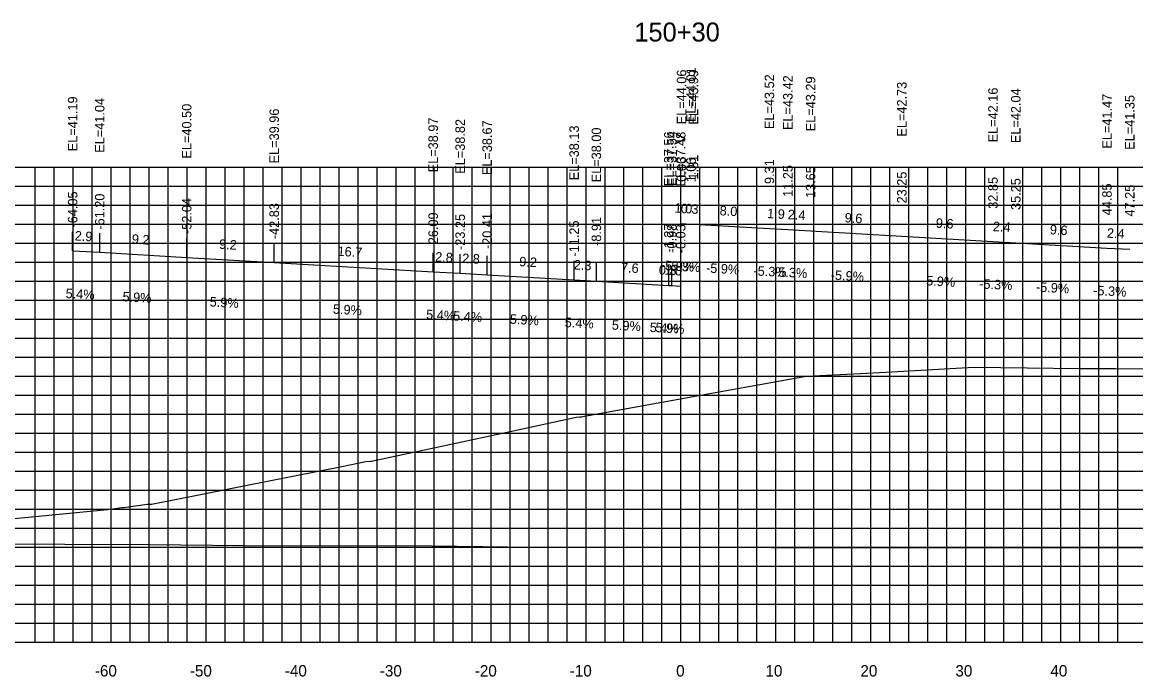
# Model space of a CAD drawing. Extents: x 1800880 to 1818864, y 245271 to 250560.
# Drawn here: x 1808999.1 to 1809116.3, y 249645.6 to 249714.4 of the extents above; entities that cross this region are included whole.
import ezdxf

# ---------------------------------------------------------------- set-up
doc = ezdxf.new("R2010")
doc.units = 0
for name, color, linetype in [('ANNO-TXT', 7, 'Continuous'), ('AXIS', 7, 'Continuous'), ('CL-CNST', 7, 'Continuous'), ('DESIGN - DRAINAGE - Bridges', 7, 'Continuous'), ('Level 32', 7, 'Continuous'), ('Level 37', 7, 'Continuous'), ('Level 46', 7, 'Continuous'), ('Level 62', 7, 'Continuous'), ('SHT-BDR', 7, 'Continuous')]:
    doc.layers.add(name, color=color, linetype=linetype)

msp = doc.modelspace()

# ---------------------------------------------------------------- linework, layer by layer
at = {"layer": 'AXIS'}
msp.add_lwpolyline([(1809068.52, 249693.28), (1809069.52, 249693.22), (1809069.77, 249693.21), (1809077.77, 249692.74), (1809079.71, 249692.64), (1809082.11, 249692.51), (1809091.71, 249691.94), (1809101.31, 249691.38), (1809103.71, 249691.25), (1809113.31, 249690.69), (1809115.71, 249690.56)], dxfattribs=at)
at = {"layer": 'CL-CNST'}
msp.add_lwpolyline([(1808995.35, 249661.96), (1809008.42, 249663.24), (1809009.59, 249663.39), (1809009.81, 249663.41), (1809010.79, 249663.54), (1809012.26, 249663.74), (1809012.28, 249663.75), (1809012.71, 249663.74), (1809012.73, 249663.74), (1809017.88, 249664.77), (1809020.67, 249665.32), (1809022.44, 249665.67), (1809032.75, 249667.7), (1809035.28, 249668.24), (1809035.78, 249668.26), (1809035.86, 249668.26), (1809050.96, 249671.5), (1809051.27, 249671.56), (1809057.44, 249672.92), (1809057.81, 249672.93), (1809058.01, 249672.94), (1809058.3, 249673.01), (1809070.52, 249675.23), (1809081.63, 249677.21), (1809087.35, 249677.5), (1809090.01, 249677.64), (1809096.79, 249678.01), (1809099.34, 249678.15), (1809104.9, 249678.09), (1809110.43, 249678.04), (1809114.2, 249678.01), (1809121.86, 249677.94)], dxfattribs=at)
at = {"layer": 'DESIGN - DRAINAGE - Bridges'}
for p, q in [((1808918.46, 249649.22), (1809218.46, 249649.22)), ((1809008.46, 249649.16), (1809008.46, 249649.22)), ((1809018.46, 249649.16), (1809018.46, 249649.22)), ((1809028.46, 249649.16), (1809028.46, 249649.22)), ((1809038.46, 249649.16), (1809038.46, 249649.22)), ((1809048.46, 249649.16), (1809048.46, 249649.22)), ((1809058.46, 249649.16), (1809058.46, 249649.22)), ((1809068.46, 249649.16), (1809068.46, 249649.22)), ((1809078.46, 249649.16), (1809078.46, 249649.22)), ((1809088.46, 249649.16), (1809088.46, 249649.22)), ((1809098.46, 249649.16), (1809098.46, 249649.22)), ((1809108.46, 249649.16), (1809108.46, 249649.22))]:
    msp.add_line(p, q, dxfattribs=at)
at = {"layer": 'Level 37'}
for p, q in [((1809004.41, 249690.4), (1809004.41, 249692.4)), ((1809007.26, 249690.25), (1809007.26, 249692.25)), ((1809016.42, 249689.71), (1809016.42, 249691.71)), ((1809025.63, 249689.17), (1809025.63, 249691.17)), ((1809042.37, 249688.19), (1809042.37, 249690.19)), ((1809045.21, 249688.04), (1809045.21, 249690.04)), ((1809048.05, 249687.88), (1809048.05, 249689.88)), ((1809057.21, 249687.35), (1809057.21, 249689.35)), ((1809059.55, 249687.22), (1809059.55, 249689.22)), ((1809067.18, 249686.77), (1809067.18, 249688.77)), ((1809067.48, 249686.75), (1809067.48, 249688.75)), ((1809068.43, 249686.7), (1809068.43, 249688.7))]:
    msp.add_line(p, q, dxfattribs=at)
at = {"layer": 'Level 46'}
for p, q in [((1808918.46, 249699.22), (1809218.46, 249699.22)), ((1809000.46, 249649.22), (1809000.46, 249699.22)), ((1809002.46, 249649.22), (1809002.46, 249699.22)), ((1809004.46, 249649.22), (1809004.46, 249699.22)), ((1809006.46, 249649.22), (1809006.46, 249699.22)), ((1809008.46, 249649.22), (1809008.46, 249699.22)), ((1809010.46, 249649.22), (1809010.46, 249699.22)), ((1809012.46, 249649.22), (1809012.46, 249699.22)), ((1809014.46, 249649.22), (1809014.46, 249699.22)), ((1809016.46, 249649.22), (1809016.46, 249699.22)), ((1809018.46, 249649.22), (1809018.46, 249699.22)), ((1809020.46, 249649.22), (1809020.46, 249699.22)), ((1809022.46, 249649.22), (1809022.46, 249699.22)), ((1809024.46, 249649.22), (1809024.46, 249699.22)), ((1809026.46, 249649.22), (1809026.46, 249699.22)), ((1809028.46, 249649.22), (1809028.46, 249699.22)), ((1809030.46, 249649.22), (1809030.46, 249699.22)), ((1809032.46, 249649.22), (1809032.46, 249699.22)), ((1809034.46, 249649.22), (1809034.46, 249699.22)), ((1809036.46, 249649.22), (1809036.46, 249699.22)), ((1809038.46, 249649.22), (1809038.46, 249699.22)), ((1809040.46, 249649.22), (1809040.46, 249699.22)), ((1809042.46, 249649.22), (1809042.46, 249699.22)), ((1809044.46, 249649.22), (1809044.46, 249699.22)), ((1809046.46, 249649.22), (1809046.46, 249699.22)), ((1809048.46, 249649.22), (1809048.46, 249699.22)), ((1809050.46, 249649.22), (1809050.46, 249699.22)), ((1809052.46, 249649.22), (1809052.46, 249699.22)), ((1809054.46, 249649.22), (1809054.46, 249699.22)), ((1809056.46, 249649.22), (1809056.46, 249699.22)), ((1809058.46, 249649.22), (1809058.46, 249699.22)), ((1809060.46, 249649.22), (1809060.46, 249699.22)), ((1809062.46, 249649.22), (1809062.46, 249699.22)), ((1809064.46, 249649.22), (1809064.46, 249699.22)), ((1809066.46, 249649.22), (1809066.46, 249699.22)), ((1809068.46, 249649.22), (1809068.46, 249699.22)), ((1809070.46, 249649.22), (1809070.46, 249699.22)), ((1809072.46, 249649.22), (1809072.46, 249699.22)), ((1809074.46, 249649.22), (1809074.46, 249699.22)), ((1809076.46, 249649.22), (1809076.46, 249699.22)), ((1809078.46, 249649.22), (1809078.46, 249699.22)), ((1809080.46, 249649.22), (1809080.46, 249699.22)), ((1809082.46, 249649.22), (1809082.46, 249699.22)), ((1809084.46, 249649.22), (1809084.46, 249699.22)), ((1809086.46, 249649.22), (1809086.46, 249699.22)), ((1809088.46, 249649.22), (1809088.46, 249699.22)), ((1809090.46, 249649.22), (1809090.46, 249699.22)), ((1809092.46, 249649.22), (1809092.46, 249699.22)), ((1809094.46, 249649.22), (1809094.46, 249699.22)), ((1809096.46, 249649.22), (1809096.46, 249699.22)), ((1809098.46, 249649.22), (1809098.46, 249699.22)), ((1809100.46, 249649.22), (1809100.46, 249699.22)), ((1809102.46, 249649.22), (1809102.46, 249699.22)), ((1809104.46, 249649.22), (1809104.46, 249699.22)), ((1809106.46, 249649.22), (1809106.46, 249699.22)), ((1809108.46, 249649.22), (1809108.46, 249699.22)), ((1809110.46, 249649.22), (1809110.46, 249699.22)), ((1809112.46, 249649.22), (1809112.46, 249699.22)), ((1809114.46, 249649.22), (1809114.46, 249699.22)), ((1808918.46, 249697.22), (1809218.46, 249697.22)), ((1808918.46, 249695.22), (1809218.46, 249695.22)), ((1808918.46, 249693.22), (1809218.46, 249693.22)), ((1808918.46, 249691.22), (1809218.46, 249691.22)), ((1808918.46, 249689.22), (1809218.46, 249689.22)), ((1808918.46, 249687.22), (1809218.46, 249687.22)), ((1808918.46, 249685.22), (1809218.46, 249685.22)), ((1808918.46, 249683.22), (1809218.46, 249683.22)), ((1808918.46, 249681.22), (1809218.46, 249681.22)), ((1808918.46, 249679.22), (1809218.46, 249679.22)), ((1808918.46, 249677.22), (1809218.46, 249677.22)), ((1808918.46, 249675.22), (1809218.46, 249675.22)), ((1808918.46, 249673.22), (1809218.46, 249673.22)), ((1808918.46, 249671.22), (1809218.46, 249671.22)), ((1808918.46, 249669.22), (1809218.46, 249669.22)), ((1808918.46, 249667.22), (1809218.46, 249667.22)), ((1808918.46, 249665.22), (1809218.46, 249665.22)), ((1808918.46, 249663.22), (1809218.46, 249663.22)), ((1808918.46, 249661.22), (1809218.46, 249661.22)), ((1808918.46, 249659.22), (1809218.46, 249659.22)), ((1808918.46, 249657.22), (1809218.46, 249657.22)), ((1808918.46, 249655.22), (1809218.46, 249655.22)), ((1808918.46, 249653.22), (1809218.46, 249653.22)), ((1808918.46, 249651.22), (1809218.46, 249651.22)), ((1808918.46, 249649.22), (1809218.46, 249649.22))]:
    msp.add_line(p, q, dxfattribs=at)
at = {"layer": 'Level 62'}
for points in [[(1809004.41, 249690.4), (1809007.26, 249690.25), (1809016.42, 249689.71), (1809025.63, 249689.17), (1809042.37, 249688.19), (1809045.21, 249688.04), (1809048.05, 249687.88), (1809057.21, 249687.35), (1809059.55, 249687.22), (1809067.18, 249686.77), (1809067.48, 249686.75), (1809068.43, 249686.7)], [(1808918.46, 249660.55), (1808939.2, 249660.09), (1808950.74, 249659.99), (1808966.95, 249659.79), (1808982.05, 249659.69), (1808994.71, 249659.57), (1809012.42, 249659.49), (1809022.47, 249659.41), (1809042.19, 249659.35), (1809050.22, 249659.27), (1809071.53, 249659.24), (1809077.98, 249659.19), (1809100.58, 249659.19), (1809105.73, 249659.16), (1809129.4, 249659.19), (1809133.49, 249659.16), (1809158.05, 249659.24), (1809161.24, 249659.23), (1809186.58, 249659.35), (1809189, 249659.35), (1809214.99, 249659.5), (1809216.75, 249659.47), (1809218.46, 249659.48)]]:
    msp.add_lwpolyline(points, dxfattribs=at)

# ---------------------------------------------------------------- texts
for s, p in [('-60', (1809006.75, 249645.62)), ('-50', (1809016.75, 249645.62)), ('-40', (1809026.75, 249645.62)), ('-30', (1809036.75, 249645.62)), ('-20', (1809046.75, 249645.62)), ('-10', (1809056.75, 249645.62)), ('0', (1809067.95, 249645.62)), ('10', (1809077.35, 249645.62)), ('20', (1809087.35, 249645.62)), ('30', (1809097.35, 249645.62)), ('40', (1809107.35, 249645.62))]:
    msp.add_text(s, height=1.2).set_placement(p)
at = {"layer": 'ANNO-TXT'}
for s, rotation, p in [('1.0', 356.6368, (1809067.76, 249694.43)), ('0.3', 356.9763, (1809068.42, 249694.38)), ('8.0', 356.6368, (1809072.51, 249694.15)), ('1.9', 356.9763, (1809077.51, 249693.85)), ('2.4', 356.9763, (1809079.68, 249693.74)), ('9.6', 356.6368, (1809085.67, 249693.4)), ('9.6', 356.6368, (1809095.27, 249692.84)), ('2.9', 356.9237, (1809004.61, 249691.5)), ('2.4', 356.9763, (1809101.28, 249692.48)), ('9.6', 356.6368, (1809107.27, 249692.15)), ('2.4', 356.9763, (1809113.28, 249691.79)), ('9.2', 356.6368, (1809010.62, 249691.16)), ('9.2', 356.6368, (1809019.81, 249690.62)), ('16.7', 356.6368, (1809032.28, 249689.88)), ('2.8', 356.9237, (1809042.56, 249689.28)), ('2.8', 356.9237, (1809045.4, 249689.13)), ('9.2', 356.6368, (1809051.41, 249688.79)), ('2.3', 356.9237, (1809057.15, 249688.45)), ('7.6', 356.6368, (1809062.12, 249688.17)), ('0.3', 356.9237, (1809066.11, 249687.93)), ('-5.9%', 356.6368, (1809066.32, 249688.4)), ('-5.3%', 356.9763, (1809066.97, 249688.35)), ('-5.9%', 356.6368, (1809071.07, 249688.12)), ('1.0', 356.6368, (1809066.7, 249687.9)), ('-5.3%', 356.9763, (1809076.07, 249687.82)), ('-5.3%', 356.9763, (1809078.24, 249687.71)), ('-5.9%', 356.6368, (1809084.21, 249687.38)), ('-5.9%', 356.6368, (1809093.81, 249686.81)), ('-5.3%', 356.9763, (1809099.84, 249686.45)), ('-5.9%', 356.6368, (1809105.81, 249686.12)), ('-5.3%', 356.9763, (1809111.84, 249685.76)), ('5.4%', 356.9237, (1809003.65, 249685.44)), ('5.9%', 356.6368, (1809009.64, 249685.1)), ('5.9%', 356.6368, (1809018.82, 249684.56)), ('5.9%', 356.6368, (1809031.79, 249683.8)), ('5.4%', 356.9237, (1809041.61, 249683.22)), ('5.4%', 356.9237, (1809044.45, 249683.07)), ('5.9%', 356.6368, (1809050.42, 249682.74)), ('5.4%', 356.9237, (1809056.2, 249682.39)), ('5.9%', 356.6368, (1809061.16, 249682.12)), ('5.4%', 356.9237, (1809065.15, 249681.87)), ('5.9%', 356.6368, (1809065.75, 249681.85))]:
    msp.add_text(s, height=1, rotation=rotation, dxfattribs=at).set_placement(p)
at = {"layer": 'DESIGN - DRAINAGE - Bridges'}
msp.add_text('>', height=1.5, dxfattribs=at).set_placement((1809067.85, 249701.47))
at = {"layer": 'Level 32'}
msp.add_text('150+30', height=2, dxfattribs=at).set_placement((1809063.55, 249712.42))
at = {"layer": 'SHT-BDR'}
for s, p in [('EL=44.06', (1809069.02, 249703.71)), ('EL=44.01', (1809070.02, 249703.95)), ('EL=43.99', (1809070.27, 249703.68)), ('EL=43.52', (1809078.27, 249703.21)), ('EL=43.42', (1809080.21, 249703.11)), ('EL=43.29', (1809082.61, 249702.98)), ('EL=42.73', (1809092.21, 249702.42)), ('EL=41.19', (1809004.91, 249700.88)), ('EL=42.16', (1809101.81, 249701.81)), ('EL=42.04', (1809104.21, 249701.73)), ('EL=41.47', (1809113.81, 249701.16)), ('EL=41.35', (1809116.21, 249701.03)), ('EL=41.04', (1809007.76, 249700.72)), ('EL=40.50', (1809016.92, 249700.11)), ('EL=39.96', (1809026.13, 249699.6)), ('EL=38.97', (1809042.87, 249698.66)), ('EL=38.82', (1809045.71, 249698.51)), ('EL=38.67', (1809048.55, 249698.36)), ('EL=38.13', (1809057.71, 249697.82)), ('EL=38.00', (1809060.05, 249697.61)), ('EL=37.56', (1809067.68, 249697.2)), ('EL=37.54', (1809067.98, 249697.23)), ('EL=37.48', (1809068.93, 249697.17)), ('0.06', (1809069.02, 249697.67)), ('1.06', (1809070.02, 249697.61)), ('1.31', (1809070.27, 249697.9)), ('9.31', (1809078.27, 249697.43)), ('11.25', (1809080.21, 249696.08)), ('13.65', (1809082.61, 249695.96)), ('23.25', (1809092.21, 249695.39)), ('32.85', (1809101.81, 249694.83)), ('35.25', (1809104.21, 249694.7)), ('44.85', (1809113.81, 249694.14)), ('47.25', (1809116.21, 249694.01)), ('-64.05', (1809004.91, 249692.86)), ('-61.20', (1809007.76, 249692.63)), ('-52.04', (1809016.92, 249692.17)), ('-42.83', (1809026.13, 249691.63)), ('-26.09', (1809042.87, 249690.65)), ('-23.25', (1809045.71, 249690.49)), ('-20.41', (1809048.55, 249690.59)), ('-8.91', (1809060.05, 249690.92)), ('-11.25', (1809057.71, 249689.8)), ('-1.27', (1809067.68, 249690.22)), ('-0.98', (1809067.98, 249690.2)), ('-0.03', (1809068.93, 249690.15))]:
    msp.add_text(s, height=1, rotation=90, dxfattribs=at).set_placement(p)

doc.saveas('drawing.dxf')
